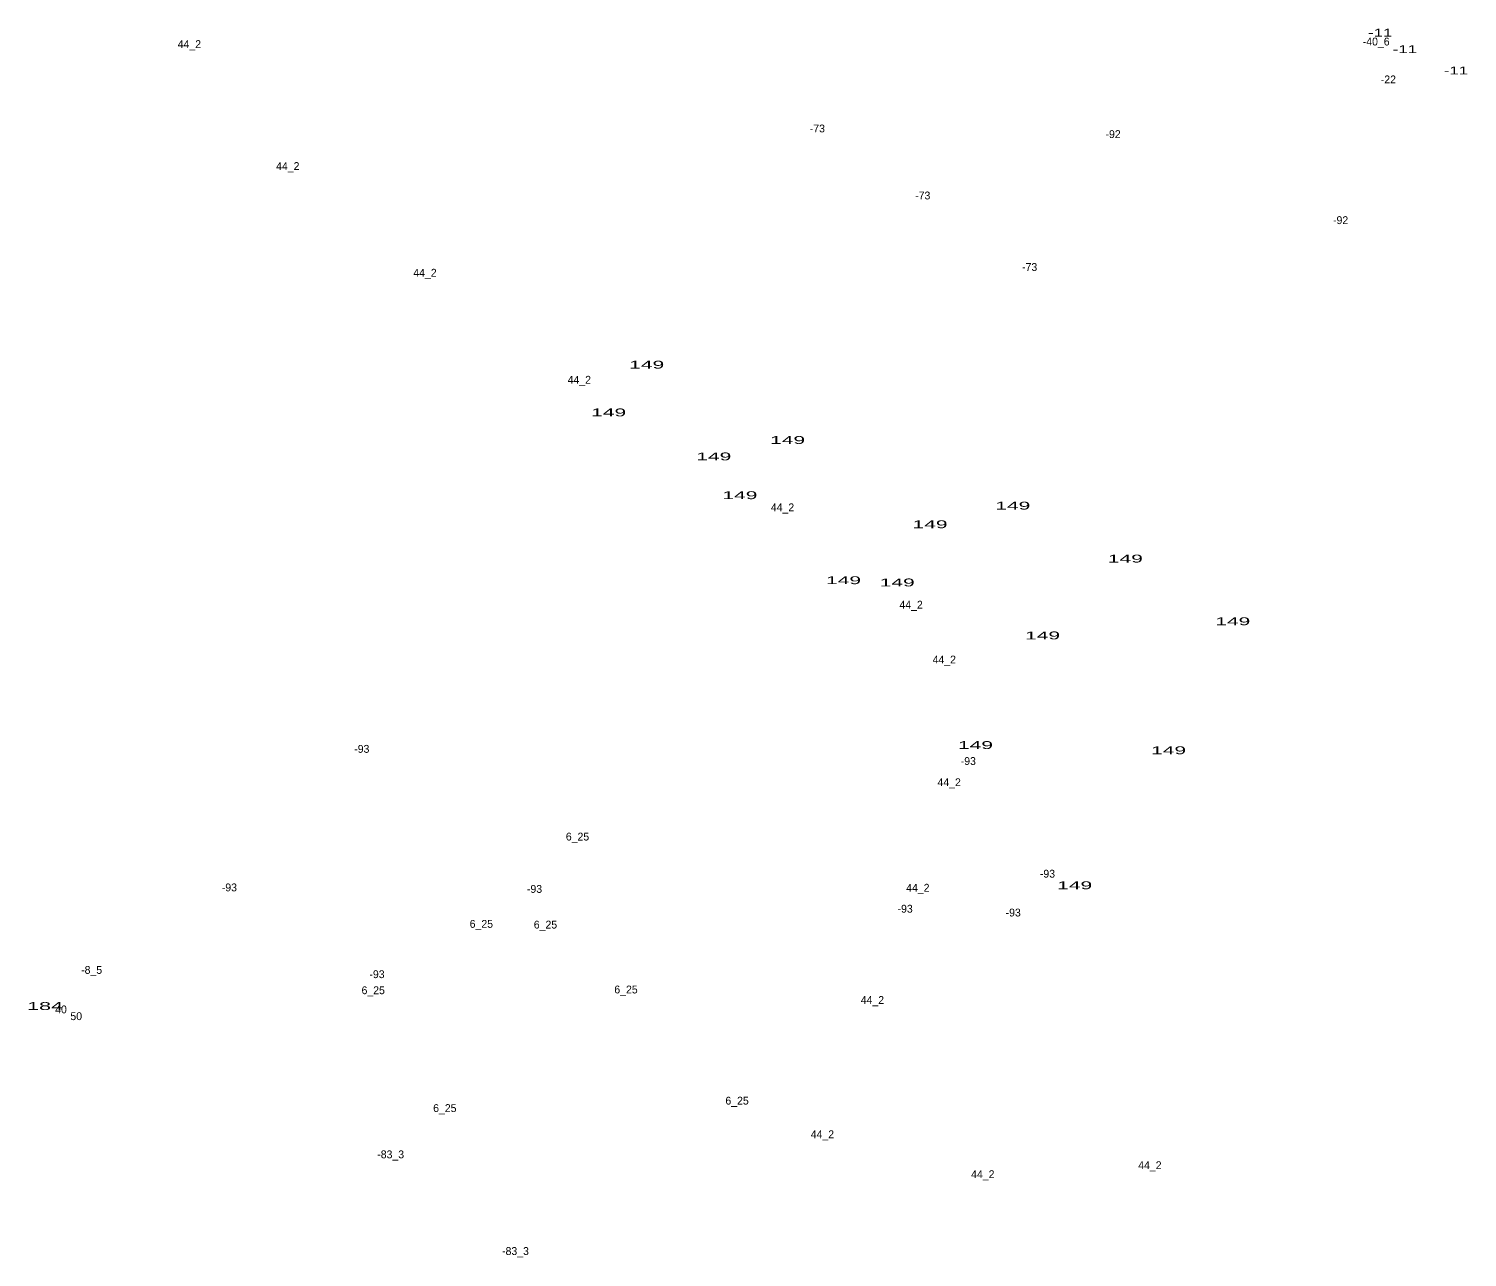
# Model space of a CAD drawing. Extents: x -659624 to -656248, y -1006345 to -1003555.
# Drawn here: x -656982 to -656248, y -1005534 to -1004908 of the extents above; entities that cross this region are included whole.
import ezdxf
from ezdxf.enums import TextEntityAlignment as Align

# ---------------------------------------------------------------- set-up
doc = ezdxf.new("R2010")
doc.units = 0
doc.header["$LTSCALE"] = 1.6
doc.layers.add('24', color=7, linetype='Continuous')

msp = doc.modelspace()

# ---------------------------------------------------------------- texts
at = {"layer": '24'}
for s, p in [('44_2', (-656899.854, -1004917.34)), ('-40_6', (-656294.406, -1004916.02)), ('-22', (-656288.185, -1004935.34)), ('-73', (-656579.481, -1004960.36)), ('-92', (-656428.62, -1004963.25)), ('44_2', (-656849.644, -1004979.55)), ('-73', (-656525.721, -1004994.55)), ('-92', (-656312.55, -1005007.13)), ('44_2', (-656779.664, -1005033.97)), ('-73', (-656471.191, -1005031.04)), ('44_2', (-656700.924, -1005088.57)), ('44_2', (-656597.264, -1005153.64)), ('44_2', (-656531.654, -1005203.3)), ('44_2', (-656514.724, -1005231.27)), ('-93', (-656811.89, -1005276.84)), ('-93', (-656502.48, -1005283.06)), ('44_2', (-656512.244, -1005293.87)), ('6_25', (-656701.84, -1005321.6)), ('-93', (-656462.11, -1005340.53)), ('-93', (-656879.44, -1005347.52)), ('-93', (-656723.77, -1005348.3)), ('44_2', (-656528.224, -1005347.71)), ('-93', (-656534.71, -1005358.4)), ('6_25', (-656750.9, -1005366.12)), ('6_25', (-656718.19, -1005366.5)), ('-93', (-656479.58, -1005360.34)), ('-8_5', (-656949.713, -1005389.61)), ('-93', (-656804.13, -1005391.79)), ('6_25', (-656806.06, -1005399.98)), ('6_25', (-656677.11, -1005399.6)), ('40', (-656965.325, -1005409.74)), ('44_2', (-656551.414, -1005404.96)), ('50', (-656957.571, -1005413.21)), ('6_25', (-656769.54, -1005460.1)), ('6_25', (-656620.44, -1005456.3)), ('44_2', (-656576.904, -1005473.45)), ('-83_3', (-656797.162, -1005483.7)), ('44_2', (-656409.854, -1005489.23)), ('44_2', (-656495.084, -1005493.81)), ('-83_3', (-656733.492, -1005533.02))]:
    msp.add_text(s, height=4, dxfattribs=at).set_placement(p, align=Align.CENTER)
for s, width, p in [('-11', 1.6, (-656292.377, -1004911.5)), ('-11', 1.6, (-656279.777, -1004919.91)), ('-11', 1.6, (-656253.727, -1004930.76)), ('149', 2, (-656666.558, -1005080.85)), ('149', 2, (-656685.958, -1005105.21)), ('149', 2, (-656594.668, -1005119.29)), ('149', 2, (-656632.328, -1005127.66)), ('149', 2, (-656619.008, -1005147.44)), ('149', 2, (-656479.798, -1005152.77)), ('149', 2, (-656522.018, -1005162.28)), ('149', 2, (-656422.368, -1005179.78)), ('149', 2, (-656566.138, -1005190.82)), ('149', 2, (-656538.758, -1005191.96)), ('149', 2, (-656367.588, -1005211.77)), ('149', 2, (-656464.588, -1005218.98)), ('149', 2, (-656498.818, -1005274.91)), ('149', 2, (-656400.298, -1005277.57)), ('149', 2, (-656448.228, -1005346.44)), ('184', 2.05, (-656973.473, -1005408.04))]:
    msp.add_text(s, height=4, dxfattribs=dict(at, width=width)).set_placement(p, align=Align.CENTER)

doc.saveas('drawing.dxf')
